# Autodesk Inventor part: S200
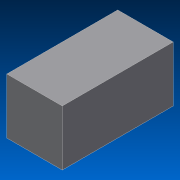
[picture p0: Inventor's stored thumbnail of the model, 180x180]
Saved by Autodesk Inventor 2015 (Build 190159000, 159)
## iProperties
Created: 2017-11
Part Number: S200
Material: Všeobecné
Document SubType Name: Modeling
Designer: navara
Mass: 2 g
Surface Area: 10 cm^2
Volume: 2 cm^3
Density: 1 g/cm^3
Appearance: Výchozí
Title: 332211
Author: navara
Last Saved By: navara
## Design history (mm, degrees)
sketch "Náčrt1"
  geometry: L1 (-5, 5)-(5, 5); L2 (5, 5)-(5, -5); L3 (5, -5)-(-5, -5); L4 (-5, -5)-(-5, 5); L5 (-5, 5)-(5, -5); L6 (5, 5)-(-5, -5); 1 further point
  constraints: 12 end point, 2 midpoint, 2 parallel, 1 horizontal, 1 perpendicular
  dimensions: "d0" = 10 distance of L2.end L3.end; "d1" = 10 distance of L1.end L2.end
extrude "Vysunutí1" new body sketch "Náčrt1" distance "d2" = 20; taper "d3" = 0 deg
node "Těleso1"
